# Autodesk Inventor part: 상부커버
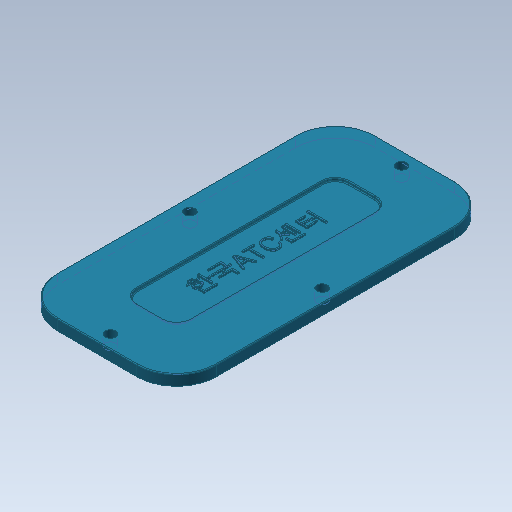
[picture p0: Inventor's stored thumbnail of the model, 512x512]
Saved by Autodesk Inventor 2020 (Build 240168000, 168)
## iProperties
Created: 2016-02
Part Number: 상부커버
Material: 강철, 연강
Document SubType Name: Modeling
Designer: mduedu
Density: 1 g/cm^3
Mass: 15.5198 g
Surface Area: 149.263 cm^2
Volume: 15.5198 cm^3
Appearance: 터키옥색
Author: mduedu
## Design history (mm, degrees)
sketch "스케치1"
  geometry: L1 (30, 60)-(-30, 60); L2 (-30, 60)-(-30, -60); L3 (-30, -60)-(30, -60); L4 (30, -60)-(30, 60); L5 (30, 60)-(-30, -60); L6 (-30, 60)-(30, -60); 1 further point
  constraints: 12 end point, 2 midpoint, 2 parallel, 1 horizontal, 1 perpendicular
  dimensions: "d0" = 60 distance of L2.end L3.end; "d2" = 120 distance of L1.end L2.end
extrude "돌출1" new body sketch "스케치1" distance "d3" = 4; taper "d4" = 0 deg
fillet "모깎기1" dims "d5" = 15
sketch "스케치2"
  geometry: L1 (30, 45)-(30, -45) reference; L2 (15, -60)-(-15, -60) reference; L3 (-30, -45)-(-30, 45) reference; L4 (-15, 60)-(15, 60) reference; L5 (25, 45)-(25, -45); L6 (15, -55)-(-15, -55); L7 (-25, -45)-(-25, 45); L8 (-15, 55)-(15, 55); A1 r 15 centre (15, 45) between (30, 45) and (15, 60) reference; A2 r 15 centre (15, -45) between (15, -60) and (30, -45) reference; A3 r 15 centre (-15, -45) between (-30, -45) and (-15, -60) reference; A4 r 15 centre (-15, 45) between (-15, 60) and (-30, 45) reference; A5 r 10 centre (15, 45) between (25, 45) and (15, 55); A6 r 10 centre (15, -45) between (15, -55) and (25, -45); A7 r 10 centre (-15, -45) between (-25, -45) and (-15, -55); A8 r 10 centre (-15, 45) between (-15, 55) and (-25, 45); 4 further points
  constraints: 8 end point, 8 point on circle, 4 centre point, 4 midpoint, 7 other
  dimensions: "d8" = 5 distance between parallel lines of L7 L3
hole "구멍1" sketch "스케치2" at (0, 55), (25, 0), (0, -55), (-25, 0) diameter "d9" = 4; stored, may be unused: countersink angle "d13" = 90 deg, drill point angle "d15" = 118 deg; dims "d10" = 6, "d11" = 4, "d12" = 2, "d14" = 8
sketch "스케치3"
  geometry: L1 (10, -40)-(-10, -40); L2 (-10, -40)-(-10, 40); L3 (-10, 40)-(10, 40); L4 (10, 40)-(10, -40); L5 (10, -40)-(-10, 40); L6 (-10, -40)-(10, 40); 1 further point
  constraints: 12 end point, 2 equal length, 2 midpoint, 1 horizontal, 1 parallel
  dimensions: "d16" = 80 distance of L1.end L2.end; "d18" = 20 distance of L2.end L3.end
extrude "돌출2" cut sketch "스케치3" distance "d19" = 1; taper "d20" = 0 deg
fillet "모깎기2" dims "d21" = 5
fillet "모깎기3" dims "d22" = 0.3
fillet "모깎기4" dims "d23" = 0.3
sketch "스케치4"
  geometry: 2 further points
  constraints: 1 coincident, 1 other
feature "엠보싱1" sketch "스케치4" dims "d0" = 60, "d2" = 120, "d12" = 2, "d24" = 0.5, "d25" = 0
node "솔리드1"
node "절단 모서리 투영1"
